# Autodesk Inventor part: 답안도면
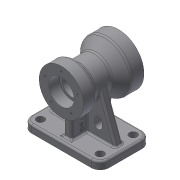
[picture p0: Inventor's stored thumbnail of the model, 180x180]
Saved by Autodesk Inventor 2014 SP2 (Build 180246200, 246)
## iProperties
Created: 2012-11
Part Number: 답안도면
Material: 일반
Document SubType Name: Modeling
Designer: 손기택
Density: 1 g/cm^3
Appearance: 기본값
Author: 손기택
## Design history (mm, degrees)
sketch "스케치1"
  geometry: L1 (-61, 40)-(61, 40); L2 (61, 40)-(61, -40); L3 (61, -40)-(-61, -40); L4 (-61, -40)-(-61, 40); 1 further point
  constraints: 8 end point, 2 parallel, 1 horizontal, 1 perpendicular
  dimensions: "d0" = 122 distance of L1.start L1.end; "d1" = 80 distance of L3.end L1.start; "d2" = 40 distance from line of L1 point (0, 0) (= 0.5 x d1); "d3" = 61 distance from line of L4 point (0, 0) (= 0.5 x d0)
extrude "돌출1" new body sketch "스케치1" distance "d4" = 12; taper "d5" = 0 deg
sketch "스케치3"
  geometry: L1 (-40, 115)-(-20, 115); L2 (-20, 115)-(-14.804, 106); L3 (-14.804, 106)-(13.315, 106); L4 (50, 120)-(50, 106); L5 (50, 106)-(30, 106); L6 (30, 106)-(30, 99); L7 (-40, 100)-(-40, 115); L8 (-54.476, 80)-(46.915, 80); L9 (40, 0)-(-40, 0) reference; L10 (13.315, 106)-(30, 120); L11 (50, 120)-(30, 120); L12 (27, 96)-(-23, 96); L13 (-23, 96)-(-23, 100); L14 (-23, 100)-(-40, 100); L15 (27, 96)-(30, 99); L16 (-40, 0)-(-40, 12) reference; 1 further point
  constraints: 28 end point, 5 parallel, 3 perpendicular, 1 horizontal
  dimensions: "d8" = 35 distance between parallel lines of L8 L1; "d9" = 80 distance between parallel lines of L9 L8; "d13" = 90 distance between parallel lines of L7 L4; "d14" = 20 distance of L1.start L1.end; "d15" = 60 deg angle of L3 L2; "d17" = 40 deg angle of L3 L10; "d18" = 40 distance from line of L4.start L8; "d19" = 20 distance of L4.start L10.end; "d20" = 26 distance between parallel lines of L8 L3; "d22" = 20 distance of L4.end L5.end; "d26" = 16 distance between parallel lines of L8 L12; "d27" = 3 distance from line of L12.start L6; "d28" = 20 distance between parallel lines of L8 L14; "d29" = 17 distance of L13.end L7.start; "d31" = 19 distance from line of L6.end L8; "d32" = 0 distance between parallel lines of L7 L16; "d33" = 26 distance between parallel lines of L5 L8
revolve "회전1" sketch "스케치3" stored, may be unused: angle "d34" = 90 deg
sketch "스케치4"
  geometry: L1 (-6, 30)-(6, 30); L2 (6, 30)-(6, -30); L3 (6, -30)-(-6, -30); L4 (-6, -30)-(-6, 30); L5 (-61, 40)-(61, 40) reference; L6 (61, -40)-(-61, -40) reference; 1 further point
  constraints: 8 end point, 2 parallel, 1 horizontal, 1 perpendicular
  dimensions: "d35" = 12 distance of L1.start L1.end; "d38" = 6 distance from line of point (0, 0) L2 (= 0.5 x d35); "d39" = 10 distance between parallel lines of L1 L5; "d40" = 10 distance between parallel lines of L6 L3
extrude "돌출2" join sketch "스케치4" stored distance "d41" = 12; taper "d42" = 0 deg
feature "면 기울기2" dims angle "d44" = 10 deg
sketch "스케치7"
  geometry: L1 (-61, 12)-(61, 12) reference; L2 (6, 12)-(6, 40.453) reference; L3 (51, 12)-(25.99, 80.714); L4 (61, 0)-(61, 12) reference; L5 (6, 12)-(6, 45.518) reference; L6 (6, 54.702)-(6, 45.518) reference; A1 r 40 centre (0, 80) between (6, 40.453) and (33.949, 58.847) reference; A2 r 26 centre (0, 80) between (6, 54.702) and (-6, 54.702) reference; 1 further point
  constraints: 2 end point, 2 point on circle, 2 point on line
  dimensions: "d45" = 10 distance from line of L4 L3.start; "d46" = 70 deg angle of L1 L3
extrude "돌출3" join sketch "스케치7" stored distance "d47" = 12; taper "d48" = 0 deg
sketch "스케치8"
  geometry: L1 (-24, 42)-(-24, 42); L2 (-18, 36)-(-18, 30); L3 (-24, 24)-(-24, 24); L4 (-30, 30)-(-30, 36); L5 (85.4, 0)-(-85.4, 0) reference; L6 (0, -25)-(0, 150) reference; A1 r 6 centre (-24, 36) between (-24, 42) and (-30, 36); A2 r 6 centre (-24, 36) between (-18, 36) and (-24, 42); A3 r 6 centre (-24, 30) between (-30, 30) and (-24, 24); A4 r 6 centre (-24, 30) between (-24, 24) and (-18, 30); 4 further points
  constraints: 8 end point, 8 point on circle, 8 tangent, 6 point on line, 4 centre point, 3 equal radius, 2 parallel, 1 horizontal, 1 perpendicular
  dimensions: "d50" = 12 distance of point (-18, 24) point (-30, 24); "d51" = 18 distance of point (-18, 42) point (-18, 24); "d53" = 6 radius of A1; "d54" = 30 distance from line of A3.centre L5; "d55" = 24 distance from line of A3.centre L6
extrude "돌출4" cut sketch "스케치8" stored distance "d56" = 12; taper "d57" = 0 deg
sketch "스케치9"
  geometry: L1 (-85.4, 0)-(85.4, 0) reference; L2 (0, -58)-(0, 68) reference; C1 r 6 at (47, 26); C2 r 6 at (47, -26); C3 r 6 at (-47, 26); C4 r 6 at (-47, -26); 1 further point
  constraints: 4 centre point, 3 symmetric about line, 3 other
  dimensions: "d58" = 26 vertical distance of C1.centre point (0, 0); "d59" = 47 horizontal distance of C1.centre point (0, 0); "d60" = 12 diameter of C1
extrude "돌출5" cut sketch "스케치9" distance "d61" = 12; taper "d62" = 0 deg
sketch "스케치10" dims "d63" = 54
  geometry: C1 r 35 at (0, 0) reference; C2 r 20 at (0, 0) reference; 7 further points
  constraints: 1 coincident, 1 vertical alignment, 8 other
  dimensions: "d99" = 27 distance of point (0, 0) point (0, 27) (derived); "d102" = 360 deg dimension on C1.centre point (0, 27) (derived)
hole "구멍1" sketch "스케치10" at (0, 27), (-25.679, 8.343), (-15.87, -21.843), (15.87, -21.843), (25.679, 8.343) diameter "d67" = 3.242; stored, may be unused: countersink angle "d71" = 90 deg, drill point angle "d73" = 118 deg; dims "d68" = 10, "d69" = 9.4, "d70" = 2, "d72" = 12
sketch "스케치11" dims "d104" = 66
  geometry: C1 r 26 at (0, 0) reference; 7 further points
  constraints: 1 coincident, 1 vertical alignment, 8 other
  dimensions: "d107" = 360 deg dimension on C1.centre point (0, -33) (derived)
hole "구멍2" sketch "스케치11" diameter "d79" = 3.242; stored, may be unused: countersink angle "d83" = 90 deg, drill point angle "d85" = 118 deg; dims "d80" = 10, "d81" = 9.4, "d82" = 2, "d84" = 12
fillet "모깎기1" dims "d86" = 14
fillet "모깎기3" dims "d91" = 3, "d92" = 3
fillet "모깎기5" dims "d94" = 5, "d95" = 0.3
chamfer "모따기1" distance "d96" = 1; stored, may be unused: second distance "d97" = 2, angle "d98" = 45 deg
sketch "스케치12"
  geometry: L1 (0.066, 10)-(-44.934, 10); L2 (-44.934, 10)-(-44.934, 16); L3 (-44.934, 16)-(0.066, 16); L4 (0.066, 16)-(0.066, 10); L5 (25, 13)-(-128, 13); L6 (-28.081, -3)-(0, -3) reference; 1 further point
  constraints: 2 end point, 1 perpendicular, 2 other
  dimensions: "d109" = 16 distance between parallel lines of L5 L6; "d110" = 45 distance of L1.start L1.end; "d111" = 6 distance of L3.end L1.start; "d112" = 3 distance between parallel lines of L1 L5
feature "엠보싱1" sketch "스케치12" dims "d0" = 122, "d1" = 80, "d2" = 40 (= 0.5 x d1), "d3" = 61 (= 0.5 x d0), "d8" = 35, "d9" = 80, "d13" = 90, "d14" = 20, "d15" = 60 deg, "d17" = 40 deg, "d18" = 40, "d19" = 20, "d20" = 26, "d22" = 20, "d26" = 16, "d27" = 3, "d28" = 20, "d29" = 17, "d31" = 19, "d32" = 0, "d33" = 26, "d113" = 0.5, "d114" = 0
node "솔리드1"
mirror "대칭1"
mirror "대칭2"
node "투영된 루프1"
